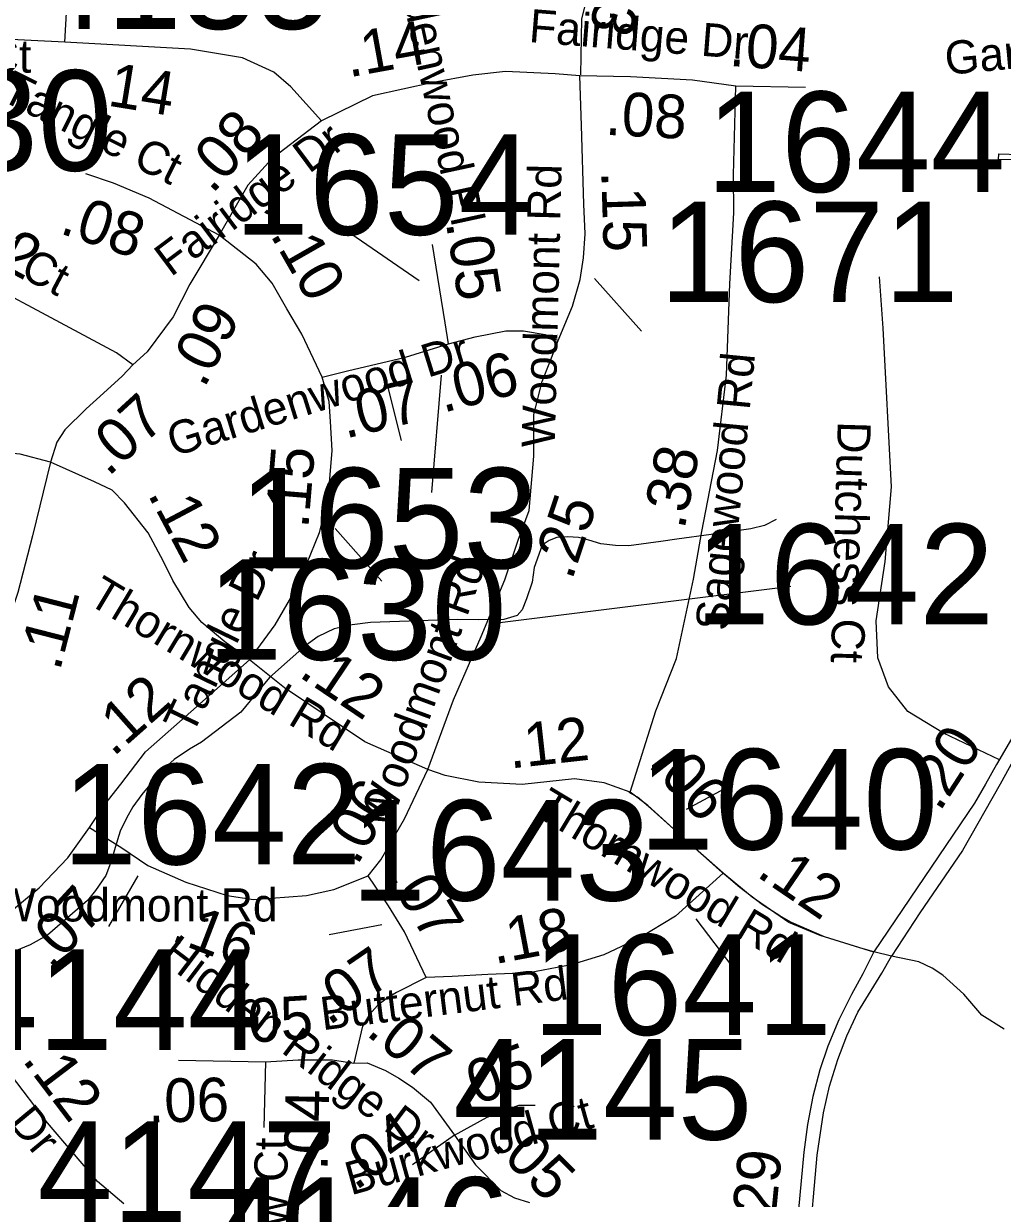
# Model space of a CAD drawing. Extents: x 1662474 to 1856135, y 779280 to 917889.
# Drawn here: x 1723593 to 1726398, y 827227 to 830593 of the extents above; entities that cross this region are included whole.
import ezdxf

# ---------------------------------------------------------------- set-up
doc = ezdxf.new("R2010")
doc.units = 0
for name, color, linetype in [('Cogo Default Point CELL', 7, 'Continuous'), ('Exist Cultural Church CELL', 7, 'Continuous'), ('Exist Hydrographic Misc Water Feature', 7, 'Continuous'), ('Exist Road Non-System Type 51', 7, 'Continuous'), ('Exist Road Non-System Type 51 Label', 7, 'Continuous'), ('Exist Road Secondary Mileage Tenths English Label', 7, 'Continuous'), ('Exist Road Secondary Type 51 Attributed', 7, 'Continuous'), ('Exist Road Secondary Type 51 Divided Attributed', 7, 'Continuous'), ('Exist Road Secondary Type 51 Label', 7, 'Continuous'), ('Prop DGN Element Guardrail', 7, 'Continuous')]:
    doc.layers.add(name, color=color, linetype=linetype)

msp = doc.modelspace()

# ---------------------------------------------------------------- linework, layer by layer
at = {"layer": 'Cogo Default Point CELL'}
for p, q in [((1724789.7, 829585), (1724761.4, 829249.6)), ((1724950.4, 828876.3), (1725791.1, 828981.2))]:
    msp.add_line(p, q, dxfattribs=at)
at = {"layer": 'Exist Cultural Church CELL'}
msp.add_lwpolyline([(1726537.2, 830142.3), (1726538.7, 830199.2), (1726462.6, 830201.3), (1726461.7, 830169.3), (1726445.7, 830169.8), (1726446.6, 830201.8), (1726386.5, 830203.5), (1726387, 830219.5), (1726447.1, 830217.8), (1726448, 830249.8), (1726464, 830249.3), (1726463.1, 830217.3), (1726539.2, 830215.2), (1726540.9, 830272.8), (1726647.3, 830269.8), (1726643.6, 830139.3)], close=True, dxfattribs=at)
at = {"layer": 'Exist Hydrographic Misc Water Feature'}
msp.add_lwpolyline([(1725749.5, 829172), (1725715.5, 829154.6), (1725677.1, 829144.7), (1725563.3, 829129), (1725464.9, 829115.4), (1725418.8, 829109), (1725326.9, 829096.1), (1725288.7, 829097.6), (1725246.5, 829101.8), (1725212.9, 829112.4), (1725182.7, 829120.4), (1725152.6, 829122.6), (1725120.6, 829120.8), (1725098.5, 829112.2), (1725078.6, 829098.7), (1725056, 829034.3), (1725049.9, 828992.6), (1725033.7, 828944.5), (1725021.6, 828912.7), (1725007.6, 828896.6), (1724969.3, 828885), (1724895.3, 828884.9), (1724835.4, 828885.4), (1724586.9, 828876.4), (1724535, 828870.1), (1724482.9, 828858.9), (1724436.8, 828836.8), (1724398.6, 828808.8), (1724298.1, 828719), (1724255.7, 828669), (1724215.5, 828619.8), (1724102.7, 828534.3), (1724068.7, 828513.6), (1724024.6, 828484.1), (1723988.3, 828452), (1723931.9, 828384.3), (1723906.1, 828348.7), (1723887.6, 828316.3), (1723869.6, 828278.8), (1723855.2, 828232.4), (1723845.2, 828194.9), (1723829, 828152.5), (1723798.8, 828108.8), (1723776.7, 828080.5), (1723662.1, 827981.1), (1723612, 827953.4), (1723567.7, 827935.5)], dxfattribs=at)
at = {"layer": 'Exist Road Non-System Type 51'}
for points in [[(1725189.2, 830445.9), (1725192.9, 830605.9), (1725206.1, 830658.7), (1725211.9, 830689.7), (1725221.5, 830726.7), (1725224.9, 830760), (1725229.9, 830793.1)], [(1726389.1, 828483.1), (1726228.6, 828559.7), (1726126.5, 828622.2), (1726071.4, 828692.1), (1726040.1, 828775.2), (1726035.6, 828881.6), (1726061.9, 829051.4), (1726079.5, 829265), (1726055.6, 829720.1), (1726044.9, 829867.1)], [(1725586.6, 828167.1), (1725390.4, 828343.7), (1725351.8, 828376.9), (1725328.1, 828389.4)], [(1726029.4, 827932.4), (1725888.1, 827976.4), (1725793.6, 828017.5), (1725760.1, 828036.2), (1725710.5, 828068.2), (1725645.1, 828117.5), (1725586.6, 828167.1)]]:
    msp.add_lwpolyline(points, dxfattribs=at)
at = {"layer": 'Exist Road Secondary Type 51 Attributed'}
for p, q in [((1723711.2, 830539.7), (1723260.8, 830560.5)), ((1725833.5, 830409.2), (1725633.4, 830413.6)), ((1724036.9, 827623.3), (1724286, 827618.2)), ((1724286, 827618.2), (1724281.8, 827430.1)), ((1724827.4, 827408.6), (1724707.1, 827322.7))]:
    msp.add_line(p, q, dxfattribs=at)
for points in [[(1723711.2, 830539.7), (1723717.1, 830640.9), (1723717.1, 830748.2), (1723710.1, 830817.5), (1723658.2, 830883.3), (1723588.9, 830931.8), (1723478, 830959.5), (1723381, 830973.3), (1723214.7, 830976.8), (1723110.7, 831004.5), (1723048.4, 831070.3), (1723006.8, 831163.8), (1723010.3, 831253.8), (1723041.4, 831347.3), (1723114.2, 831506.6)], [(1724446.8, 830313.6), (1724359.1, 830411.6), (1724310.6, 830453.2), (1724220.5, 830494.7), (1724071.5, 830519), (1723711.2, 830539.7)], [(1725187, 830442.6), (1725116.1, 830448.3), (1724974.1, 830455.2), (1724880.5, 830444.8), (1724766.2, 830424.1), (1724592.9, 830386), (1724446.8, 830313.6)], [(1725125.1, 829684.5), (1725165.8, 829783.4), (1725188, 829859.2), (1725197.7, 829921.1), (1725202.3, 829990.4), (1725198.6, 830075.7), (1725191.7, 830300.8), (1725187, 830442.6)], [(1725633.4, 830413.6), (1725509.6, 830430.2), (1725331.5, 830439.7), (1725187, 830442.6)], [(1725330.7, 828390.8), (1725404.7, 828623.6), (1725463.7, 828773.5), (1725512.4, 829001.4), (1725536.5, 829137.2), (1725581.4, 829369.1), (1725607.2, 829584.9), (1725616.2, 829847.1), (1725627.8, 830050.5), (1725626.9, 830159.5), (1725633.4, 830413.6)], [(1724446.8, 830313.6), (1724305.4, 830205.9), (1724236.1, 830129.7), (1724153.7, 829986.6)], [(1724153.7, 829986.6), (1723952.6, 830092.2), (1723850.8, 830135.1), (1723771.1, 830161.9)], [(1724153.7, 829986.6), (1724069.8, 829845.7), (1724022.2, 829752.3), (1723947.2, 829652.4), (1723905.9, 829614.9)], [(1724448.4, 829579.3), (1724389.9, 829703.3), (1724347.6, 829775.2), (1724305.4, 829849.2), (1724259.8, 829903), (1724153.7, 829986.6)], [(1724810.9, 829675), (1724800.6, 829735), (1724764.6, 829959.3)], [(1723905.9, 829614.9), (1723859.2, 829649.7), (1723672, 829749.3), (1723496.6, 829843), (1723337.1, 829922.2)], [(1724810.9, 829675), (1724887.3, 829694.8), (1724974.5, 829712.2), (1725025.3, 829712.2), (1725087.2, 829702.1), (1725125.1, 829684.5)], [(1724448.4, 829579.3), (1724521.2, 829597.5), (1724687.7, 829637.4), (1724810.9, 829675)], [(1724751.3, 828456.1), (1724824.7, 828655.4), (1724904.3, 828836.7), (1724971.8, 828998.6), (1725009.9, 829112.9), (1725041.4, 829197.3), (1725055.3, 829353.2), (1725054.9, 829473.1), (1725079.3, 829567.7), (1725100.4, 829622.7), (1725125.1, 829684.5)], [(1723905.9, 829614.9), (1723875.7, 829582.9), (1723821.9, 829534.2), (1723772.1, 829488.6), (1723711.3, 829429), (1723688.8, 829393.5), (1723670.1, 829335.9)], [(1724240, 828770.2), (1724313.5, 828869.7), (1724379.3, 828981.9), (1724441.2, 829134.4), (1724465.4, 829231.4), (1724476.9, 829369.9), (1724472.7, 829452.4), (1724468.5, 829509.5), (1724448.4, 829579.3)], [(1723670.1, 829335.9), (1723583.1, 829358.8), (1723499.8, 829366.7), (1723358.6, 829371.4), (1723123.3, 829369.4)], [(1723670.1, 829335.9), (1723618.8, 829124.9), (1723577.1, 828962.4), (1723516.3, 828783.8)], [(1724240, 828770.2), (1724169.6, 828821), (1724103.8, 828877.1), (1724067.2, 828919.5), (1724020.9, 828997.5), (1723994, 829051.1), (1723950.1, 829134), (1723882.5, 829220), (1723846.8, 829255.7), (1723796.5, 829280.2), (1723670.1, 829335.9)], [(1723781.9, 828289.6), (1723825.8, 828355.4), (1723872.1, 828413.9), (1723942.8, 828506.6), (1724072.1, 828621.1), (1724240, 828770.2)], [(1724751.3, 828456.1), (1724570.7, 828534.7), (1724341, 828689.4), (1724240, 828770.2)], [(1724580, 828150.7), (1724616.6, 828197), (1724684.9, 828314), (1724751.3, 828456.1)], [(1725330.7, 828390.8), (1725256.8, 828417.6), (1725171.4, 828429.3), (1725021.2, 828412.6), (1724897.1, 828419.7), (1724801.2, 828438.5), (1724751.3, 828456.1)], [(1725597.3, 828158.6), (1725517, 828229.1), (1725381.6, 828352.9), (1725330.7, 828390.8)], [(1723542.6, 828037.9), (1723638.3, 828116.6), (1723719.9, 828202.4), (1723781.9, 828289.6)], [(1723781.9, 828289.6), (1723874.6, 828231.1), (1723948.7, 828180.5), (1724057.7, 828133.1), (1724176.1, 828095.2), (1724252, 828083.4), (1724403.6, 828095.2), (1724481.8, 828111.8), (1724580, 828150.7)], [(1725597.3, 828158.6), (1725461, 828035.3), (1725356.4, 827972.2), (1725255.8, 827925), (1725161.6, 827895.7), (1725041.3, 827873), (1724923.5, 827868.3), (1724821, 827862.6), (1724746.9, 827859.7)], [(1726029.5, 827933.3), (1725989.1, 827945.1), (1725875.7, 827980.4), (1725785.9, 828017.8), (1725680.2, 828089.9), (1725597.3, 828158.6)], [(1724746.9, 827859.7), (1724684.2, 827990.6), (1724638.9, 828065), (1724580, 828150.7)], [(1726080.1, 827921), (1726029.5, 827933.3)], [(1726402.8, 827711.6), (1726338.1, 827751.8), (1726286.6, 827811.9), (1726226.5, 827866.4), (1726196, 827886.7), (1726158.1, 827904.8), (1726080.1, 827921)], [(1724746.9, 827859.7), (1724661.4, 827817), (1724635.7, 827801.8), (1724607.3, 827780), (1724584.4, 827754.3), (1724564.6, 827720.2), (1724539.3, 827614.5)], [(1723880.4, 827211.6), (1723804.8, 827275.9), (1723662.1, 827443.1), (1723555.8, 827582.7), (1723468.8, 827714.3)], [(1724286, 827618.2), (1724380.3, 827623.8), (1724478.3, 827623.8), (1724539.3, 827614.5)], [(1724539.3, 827614.5), (1724577.1, 827615.3), (1724629.8, 827593.2), (1724668.6, 827571.4), (1724707.1, 827546), (1724758.7, 827503.1), (1724827.4, 827408.6)], [(1724827.4, 827408.6), (1724921.5, 827459.8), (1725011.7, 827494.2), (1725059, 827494.2)], [(1724827.4, 827408.6), (1724887.5, 827322.7), (1724960.6, 827249.7), (1724999.2, 827228.2), (1725042.2, 827215.3)]]:
    msp.add_lwpolyline(points, dxfattribs=at)
at = {"layer": 'Exist Road Secondary Type 51 Divided Attributed'}
for p, q in [((1726349.3, 828413.4), (1726317, 828359.2)), ((1726317, 828359.2), (1726029.5, 827933.3))]:
    msp.add_line(p, q, dxfattribs=at)
for points in [[(1726549.5, 828709.3), (1726473.8, 828565), (1726390.8, 828414.1), (1726283.4, 828224), (1726160.9, 828045.5), (1726080.1, 827921)], [(1726511.2, 828718.1), (1726443.3, 828578.1), (1726443.3, 828578.1), (1726380.8, 828470.3), (1726380.8, 828470.3), (1726349.3, 828413.4)], [(1726029.5, 827933.3), (1725997.3, 827870.8), (1725965, 827811.4), (1725928.6, 827738.9), (1725897.5, 827663.1), (1725874.5, 827594.9), (1725854.3, 827518.5), (1725839.2, 827439), (1725828.5, 827359.3), (1725820.9, 827277.8), (1725813, 827195), (1725806.2, 827111), (1725798.9, 827029.4), (1725791.4, 826948.8), (1725785, 826868.6), (1725777.5, 826789.8), (1725770.7, 826707.6), (1725763.2, 826628.1), (1725757.1, 826548.4), (1725750.5, 826469.4), (1725747.6, 826427.1)], [(1725786.3, 826424.7), (1725813.7, 826735.8), (1725843.2, 827080), (1725866.6, 827350.8), (1725884.6, 827472.3), (1725902.4, 827548.1), (1725926.4, 827624.8), (1725951.4, 827693.1), (1725982.8, 827760.1), (1726051.9, 827872.6), (1726080.1, 827921)]]:
    msp.add_lwpolyline(points, dxfattribs=at)
at = {"layer": 'Exist Road Secondary Type 51 Label'}
for points in [[(1724530.5, 829990.8), (1724726.1, 829856.7)], [(1724530.5, 829990.8), (1724726.1, 829856.7)], [(1725363.2, 829711.3), (1725229.1, 829862.4)], [(1724675.7, 829398.2), (1724631, 829577)], [(1724675.7, 829398.2), (1724631, 829577)], [(1724619.9, 828995.4), (1724485.8, 829146.4)], [(1724619.9, 828995.4), (1724485.8, 829146.4)], [(1725626.1, 828413.9), (1725491.8, 828341.3)], [(1723837.4, 828005.7), (1723921.3, 828151.2)], [(1723837.4, 828005.7), (1723921.3, 828151.2)], [(1725626.1, 827888.4), (1725519.9, 828028.2)], [(1725626.1, 827888.4), (1725519.9, 828028.2)], [(1724469, 827983.3), (1724619.9, 828011.4)], [(1724469, 827983.3), (1724619.9, 828011.4)]]:
    msp.add_lwpolyline(points, dxfattribs=at)

# ---------------------------------------------------------------- texts
at = {"layer": 'Cogo Default Point CELL'}
for s, p in [('4135', (1723617, 830577.2)), ('1630', (1722991.5, 830170.9)), ('1644', (1725549, 830109.9)), ('1654', (1724196.8, 829987.5)), ('1671', (1725415.5, 829794.7)), ('1653', (1724210.8, 829031.8)), ('1642', (1725517, 828871.4)), ('1630', (1724120.2, 828769.9)), ('1640', (1725356.4, 828226.5)), ('1642', (1723704.1, 828183.6)), ('1643', (1724531.5, 828080.2)), ('1641', (1725051.9, 827695.3)), ('4144', (1723420.5, 827652.3)), ('4145', (1724824.5, 827395.4)), ('4147', (1723633.6, 827159.8)), ('4146', (1724130.3, 826999.5))]:
    msp.add_text(s, height=288, dxfattribs=at).set_placement(p)
at = {"layer": 'Exist Road Non-System Type 51 Label'}
for s, rotation, p in [('Gardner Ln', 5.3222, (1726236.8, 830445.4)), ('Dutchess Ct', 268.345, (1725925.8, 829454))]:
    msp.add_text(s, height=95, rotation=rotation, dxfattribs=at).set_placement(p)
at = {"layer": 'Exist Road Secondary Mileage Tenths English Label'}
for s, rotation, p in [('.03', 252.4449, (1725280.8, 830804.1)), ('.14', 10.3004, (1724525.1, 830438.2)), ('.04', 355.695, (1725612.6, 830471.7)), ('.14', 350.7579, (1723785.3, 830365.4)), ('.08', 47.7136, (1724133.4, 830101.9)), ('.15', 271.7633, (1725248.1, 830169)), ('.12', 331.8884, (1723393.6, 829964.8)), ('.15', 85.2451, (1724408.8, 829144.3)), ('.38', 79.0387, (1725486.4, 829140.9)), ('.12', 297.908, (1723947.2, 829244.8)), ('.25', 71.5572, (1725163.9, 828995.1)), ('.12', 326.033, (1724378.1, 828723.8)), ('.12', 41.5535, (1723849.8, 828489.8)), ('.12', 6.3442, (1724987.4, 828458.3)), ('.20', 57.0388, (1726217.4, 828331.8)), ('.06', 313.0506, (1725379.3, 828467.7)), ('.06', 59.7319, (1724548.5, 828177.9)), ('.12', 325.6862, (1725689.4, 828152.1)), ('.07', 47.3874, (1723673.7, 827877.4)), ('.07', 301.3372, (1724632.5, 828148.9)), ('.18', 10.6845, (1724942.5, 827897.7)), ('.16', 338.9713, (1724012.3, 827966.6)), ('.07', 34.3682, (1724467.3, 827720.4)), ('.05', 3.575, (1724193.4, 827670.2)), ('.07', 320.2073, (1724571.1, 827697.7)), ('.05', 20.846, (1724848.9, 827477)), ('.12', 307.2591, (1723587.1, 827623)), ('.06', 0.9872, (1723950.6, 827444.4)), ('.04', 88.7541, (1724463.9, 827305.8)), ('.04', 35.5257, (1724544.4, 827247.5)), ('.05', 315.0125, (1724931.2, 827374.8))]:
    msp.add_text(s, height=125, rotation=rotation, dxfattribs=at).set_placement(p)
at = {"layer": 'Exist Road Secondary Type 51 Label'}
for s, rotation, p in [('Gardenwood Pl', 282.2292, (1724635.9, 830864.1)), ('Fairidge Dr', 355.4635, (1725039.1, 830539.8)), ('Tangle Ct', 333.4222, (1723523, 830375.3)), ('Fairidge Dr', 36.7306, (1724015, 829865.3)), ('Bellwood Ct', 332.1446, (1723092, 830126.9)), ('Woodmont Rd', 88.6125, (1725115, 829377.4)), ('Gardenwood Dr', 17.2905, (1724022.5, 829350.9)), ('Sagewood Rd', 84.4958, (1725612.3, 828850.8)), ('Tangle Dr', 64.0921, (1724076.1, 828550.7)), ('Woodmont Rd', 69.927, (1724640.1, 828280.5)), ('Thornwood Rd', 329.0222, (1723772.3, 828933.2)), ('Thornwood Rd', 329.0222, (1725053.6, 828326.1)), ('Hidden Ridge Dr', 322.8534, (1723978.9, 827911.9)), ('Butternut Rd', 7.2183, (1724449.5, 827708.5)), ('Tangle Dr', 309.6311, (1723276.8, 827769.6)), ('Burkwood Ct', 15.6012, (1724530.6, 827235.4)), ('Crossbow Ct', 90, (1724349.5, 826674))]:
    msp.add_text(s, height=95, rotation=rotation, dxfattribs=at).set_placement(p)
for s, p in [('Kingsdale Ct', (1722895, 830451.9)), ('Woodmont Rd', (1723508.8, 828020.3))]:
    msp.add_text(s, height=95, dxfattribs=at).set_placement(p)
at = {"layer": 'Prop DGN Element Guardrail'}
for s, rotation, p in [('.08', 356.9473, (1725258, 830274.2)), ('.08', 341.4138, (1723693, 829992.8)), ('.05', 279.1152, (1724802.8, 830022.3)), ('.10', 299.7252, (1724297.9, 829988.4)), ('.09', 63.0112, (1724110.9, 829545.4)), ('.06', 14.5478, (1724795, 829477.2)), ('.07', 13.4754, (1724515, 829403.2)), ('.07', 42.4896, (1723835.5, 829292.4)), ('.11', 75.6285, (1723696.9, 828735.2)), ('.29', 84.4955, (1725743.8, 827129.3))]:
    msp.add_text(s, height=125, rotation=rotation, dxfattribs=at).set_placement(p)

doc.saveas('drawing.dxf')
